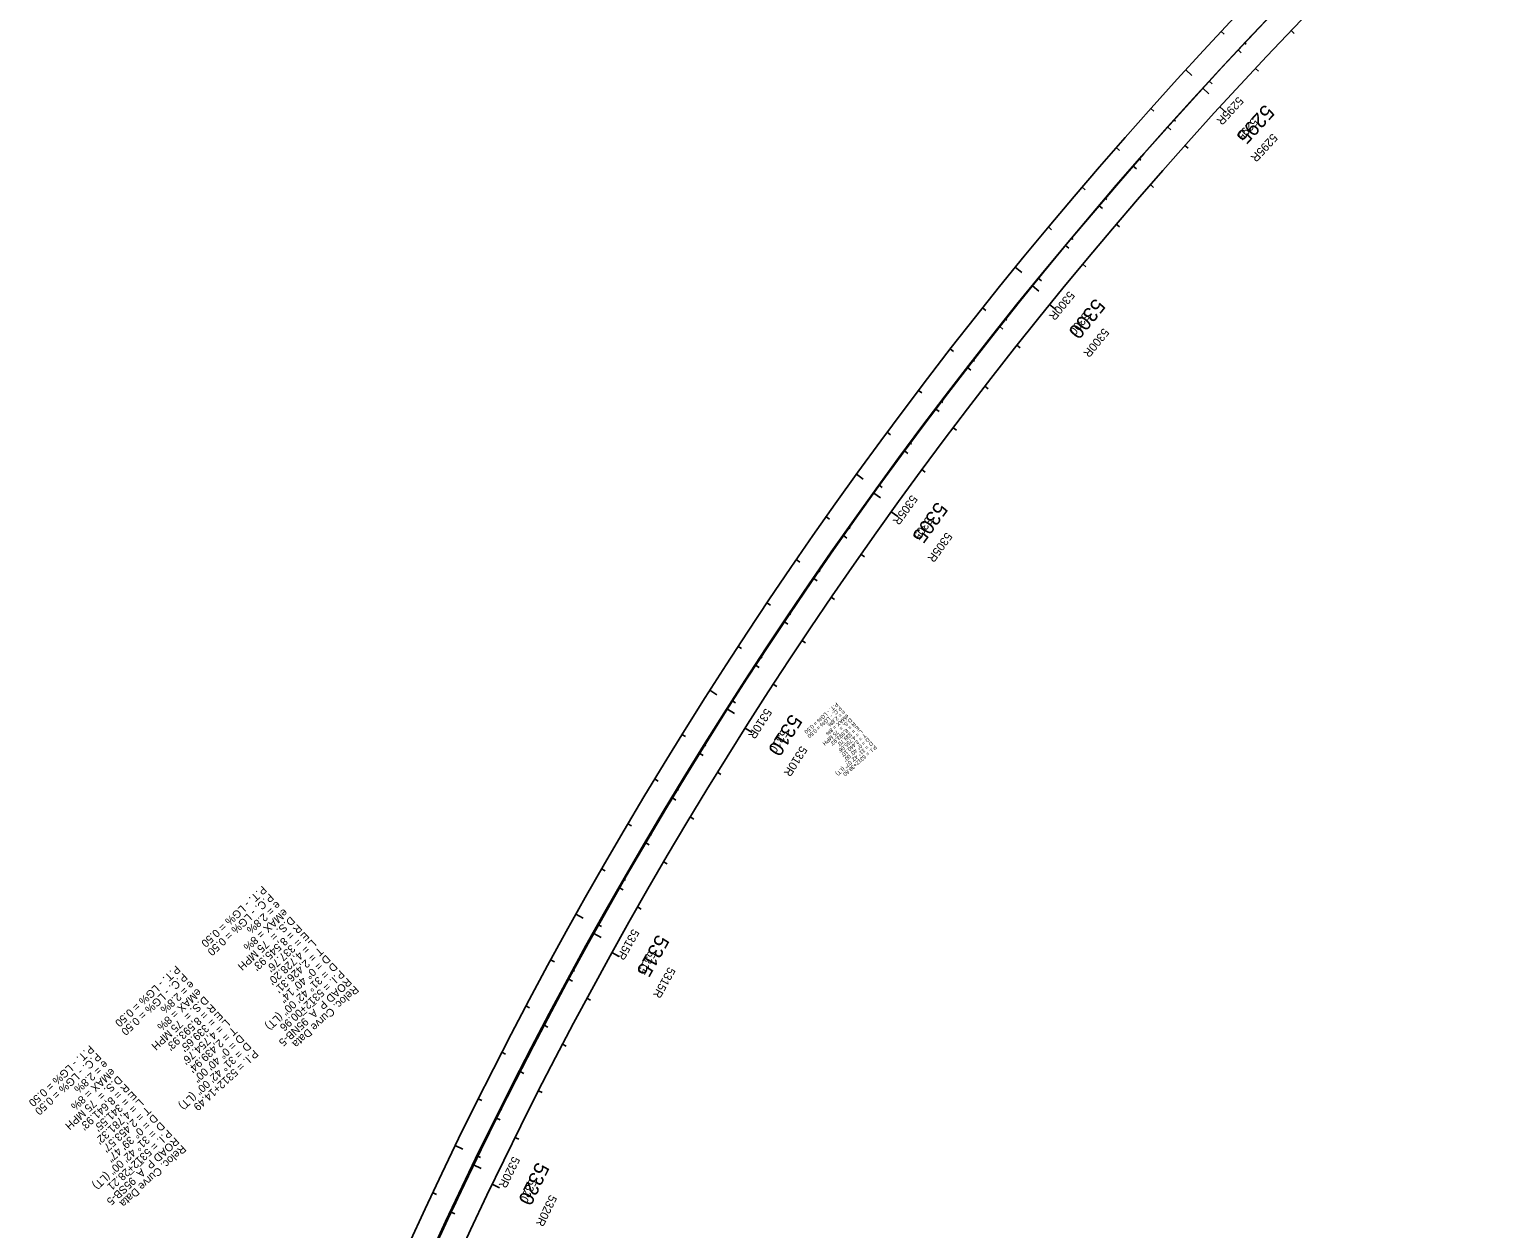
# Model space of a CAD drawing. Extents: x 2160876 to 2175990, y 601436 to 618246.
# Drawn here: x 2160945 to 2163737, y 603160 to 605458 of the extents above; entities that cross this region are included whole.
import ezdxf

# ---------------------------------------------------------------- set-up
doc = ezdxf.new("R2010")
doc.units = 0
for name, color, linetype in [('BNDY-ADJ', 7, 'Continuous'), ('BNDY-ADJ-TXT', 7, 'Continuous'), ('RD_DTM_Major2', 7, 'Continuous'), ('RD_EX_BldgApp_Steps', 7, 'Continuous'), ('RD_EX_DV_TX_Prop', 7, 'Continuous'), ('RD_EX_Parking_Conc', 7, 'Continuous'), ('RD_HC_Cl', 7, 'Continuous'), ('RD_HC_Data_Tic', 7, 'Continuous'), ('RD_HC_TX_Sta50', 7, 'Continuous')]:
    doc.layers.add(name, color=color, linetype=linetype)

msp = doc.modelspace()

# ---------------------------------------------------------------- linework, layer by layer
at = {"layer": 'BNDY-ADJ'}
msp.add_arc((2169535, 599544.7), 8593.9, 132.71947, 164.41949, dxfattribs=at)
at = {"layer": 'BNDY-ADJ-TXT'}
for radius in [8641.9, 8545.9]:
    msp.add_arc((2169535, 599544.7), radius, 132.71947, 164.41949, dxfattribs=at)
at = {"layer": 'RD_DTM_Major2'}
for p, q in [((2163261.1, 605417.9), (2163267, 605412.4)), ((2163193.2, 605344.5), (2163205, 605333.7)), ((2163126.2, 605270.3), (2163132.1, 605265)), ((2163060, 605195.4), (2163066, 605190.1)), ((2162994.7, 605119.6), (2163000.8, 605114.4)), ((2162930.2, 605043.2), (2162936.4, 605038)), ((2162866.7, 604965.9), (2162879.1, 604955.8)), ((2162804.1, 604888), (2162810.3, 604883)), ((2162742.4, 604809.3), (2162748.7, 604804.4)), ((2162681.6, 604729.9), (2162687.9, 604725.1)), ((2162621.7, 604649.8), (2162628.1, 604645)), ((2162562.8, 604569), (2162575.7, 604559.7)), ((2162504.8, 604487.5), (2162511.3, 604482.9)), ((2162447.7, 604405.4), (2162454.3, 604400.9)), ((2162391.7, 604322.6), (2162398.3, 604318.2)), ((2162336.5, 604239.2), (2162343.2, 604234.8)), ((2162282.4, 604155.1), (2162295.9, 604146.5)), ((2162229.3, 604070.4), (2162236.1, 604066.2)), ((2162177.1, 603985.1), (2162183.9, 603980.9)), ((2162125.9, 603899.2), (2162132.8, 603895.1)), ((2162075.8, 603812.7), (2162082.7, 603808.7)), ((2162026.6, 603725.6), (2162040.6, 603717.8)), ((2161978.5, 603637.9), (2161985.5, 603634.1)), ((2161931.3, 603549.7), (2161938.4, 603546)), ((2161885.3, 603461), (2161892.4, 603457.3)), ((2161840.2, 603371.7), (2161847.4, 603368.1)), ((2161796.2, 603281.9), (2161810.6, 603274.9)), ((2161753.2, 603191.6), (2161760.5, 603188.2))]:
    msp.add_line(p, q, dxfattribs=at)
at = {"layer": 'RD_EX_BldgApp_Steps'}
for p, q in [((2163273.3, 605431.5), (2163276.3, 605428.8)), ((2163205.2, 605358.3), (2163211.1, 605352.9)), ((2163138, 605284.3), (2163140.9, 605281.6)), ((2163071.6, 605209.5), (2163074.6, 605206.9)), ((2163006, 605134), (2163009.1, 605131.4)), ((2162941.4, 605057.7), (2162944.5, 605055.1)), ((2162877.7, 604980.6), (2162883.9, 604975.6)), ((2162814.8, 604902.8), (2162817.9, 604900.4)), ((2162752.9, 604824.3), (2162756, 604821.9)), ((2162691.9, 604745.1), (2162695, 604742.7)), ((2162631.8, 604665.2), (2162635, 604662.8)), ((2162572.6, 604584.6), (2162579.1, 604579.9)), ((2162514.4, 604503.3), (2162517.7, 604500.9)), ((2162457.1, 604421.3), (2162460.4, 604419)), ((2162400.8, 604338.6), (2162404.1, 604336.4)), ((2162345.5, 604255.4), (2162348.8, 604253.2)), ((2162291.1, 604171.4), (2162297.8, 604167.1)), ((2162237.7, 604086.9), (2162241.1, 604084.8)), ((2162185.3, 604001.7), (2162188.7, 603999.6)), ((2162133.9, 603915.9), (2162137.3, 603913.9)), ((2162083.5, 603829.6), (2162087, 603827.6)), ((2162034.1, 603742.6), (2162041.1, 603738.7)), ((2161985.7, 603655.1), (2161989.2, 603653.2)), ((2161938.3, 603567), (2161941.9, 603565.2)), ((2161892, 603478.4), (2161895.6, 603476.6)), ((2161846.7, 603389.3), (2161850.3, 603387.5)), ((2161802.5, 603299.6), (2161809.7, 603296.1)), ((2161759.2, 603209.4), (2161762.9, 603207.7))]:
    msp.add_line(p, q, dxfattribs=at)
msp.add_arc((2169530.8, 599540.9), 8593.9, 132.71947, 164.42145, dxfattribs=at)
at = {"layer": 'RD_HC_Cl'}
for p, q in [((2163228.5, 605453.3), (2163234.4, 605447.9)), ((2163362.6, 605455.2), (2163368.4, 605449.7)), ((2163160.6, 605380), (2163172.4, 605369.2)), ((2163293.9, 605382.6), (2163299.7, 605377.2)), ((2163093.5, 605305.8), (2163099.5, 605300.5)), ((2163226, 605309.2), (2163237.8, 605298.4)), ((2163027.3, 605230.9), (2163033.3, 605225.6)), ((2163159, 605235), (2163164.9, 605229.6)), ((2162961.9, 605155.2), (2162968, 605150)), ((2163092.8, 605160), (2163098.8, 605154.7)), ((2163027.5, 605084.2), (2163033.6, 605079)), ((2162897.4, 605078.8), (2162903.6, 605073.6)), ((2162833.8, 605001.6), (2162846.2, 604991.5)), ((2162963.2, 605007.7), (2162969.3, 605002.6)), ((2162771.1, 604923.7), (2162777.4, 604918.7)), ((2162899.7, 604930.4), (2162912.1, 604920.3)), ((2162709.4, 604845.1), (2162715.7, 604840.2)), ((2162837.1, 604852.4), (2162843.4, 604847.4)), ((2162775.5, 604773.7), (2162781.8, 604768.8)), ((2162648.5, 604765.7), (2162654.9, 604760.9)), ((2162714.8, 604694.2), (2162721.1, 604689.4)), ((2162588.5, 604685.7), (2162595, 604680.9)), ((2162655, 604614.1), (2162661.4, 604609.3)), ((2162529.5, 604605), (2162542.5, 604595.6)), ((2162471.4, 604523.6), (2162478, 604519)), ((2162596.1, 604533.2), (2162609.1, 604523.9)), ((2162414.3, 604441.5), (2162420.9, 604437)), ((2162538.2, 604451.7), (2162544.8, 604447.1)), ((2162358.1, 604358.8), (2162364.7, 604354.3)), ((2162481.3, 604369.5), (2162487.9, 604364.9)), ((2162302.9, 604275.4), (2162309.6, 604271)), ((2162425.3, 604286.6), (2162432, 604282.2)), ((2162248.6, 604191.4), (2162262.1, 604182.8)), ((2162370.3, 604203.1), (2162377, 604198.7)), ((2162195.3, 604106.8), (2162202.1, 604102.6)), ((2162316.3, 604118.9), (2162329.8, 604110.4)), ((2162143, 604021.5), (2162149.9, 604017.4)), ((2162263.3, 604034.1), (2162270.1, 604029.9)), ((2162091.7, 603935.7), (2162098.6, 603931.6)), ((2162211.2, 603948.7), (2162218.1, 603944.6)), ((2162160.2, 603862.8), (2162167.1, 603858.7)), ((2162041.4, 603849.3), (2162048.4, 603845.3)), ((2162110.2, 603776.2), (2162117.1, 603772.2)), ((2161992.1, 603762.3), (2162006.1, 603754.5)), ((2162061.2, 603689), (2162075.2, 603681.2)), ((2161943.8, 603674.7), (2161950.9, 603670.9)), ((2162013.2, 603601.3), (2162020.2, 603597.5)), ((2161896.5, 603586.6), (2161903.6, 603582.9)), ((2161850.3, 603498), (2161857.4, 603494.3)), ((2161966.3, 603513), (2161973.3, 603509.2)), ((2161805.1, 603408.8), (2161812.2, 603405.2)), ((2161920.3, 603424.1), (2161927.5, 603420.5)), ((2161875.5, 603334.8), (2161882.6, 603331.2)), ((2161760.9, 603319.1), (2161775.3, 603312.1)), ((2161831.6, 603244.9), (2161846.1, 603237.9)), ((2161717.7, 603228.9), (2161724.9, 603225.4))]:
    msp.add_line(p, q, dxfattribs=at)

# ---------------------------------------------------------------- texts
at = {"layer": 'RD_EX_BldgApp_Steps'}
for s, height, rotation, p in [('5295', 28, 227.3964, (2163312.3, 605315.2)), ('5300', 28, 230.7299, (2162987.1, 604943.9)), ('5305', 28, 234.0634, (2162684, 604554.2)), ('P.T. - LG% = 0.50', 7.5, 221.9367, (2162491, 604168.4)), ('P.C. - LG% = 0.50', 7.5, 221.9367, (2162497.7, 604160.9)), ('5310', 28, 237.3969, (2162404.1, 604147.6)), ('D.S. =  75 MPH ', 7.5, 221.9367, (2162517.7, 604138.6)), ('eMAX = 8%', 7.5, 221.9367, (2162511, 604146)), ('e = 2.8%', 7.5, 221.9367, (2162504.3, 604153.5)), ("R = 8,593.93'", 7.5, 221.9367, (2162524.4, 604131.2)), ("E = 339.70'", 7.5, 221.9367, (2162531.1, 604123.7)), ("L = 4,755.06'", 7.5, 221.9367, (2162537.8, 604116.3)), ("T = 2,440.10'", 7.5, 221.9367, (2162544.4, 604108.8)), ('    = 31° 42\' 07" (LT)', 7.5, 221.9367, (2162557.8, 604094)), ('P.I. = 5312+38.60', 7.5, 221.9367, (2162564.5, 604086.5)), ('D = 0° 40\' 00"', 7.5, 221.9367, (2162551.1, 604101.4)), ('D', 7.5, 221.9367, (2162557.8, 604094)), ('5315', 28, 240.7304, (2162148.2, 603725.3)), ('5320', 28, 244.0639, (2161917.4, 603289.1))]:
    msp.add_text(s, height=height, rotation=rotation, dxfattribs=at).set_placement(p)
at = {"layer": 'RD_EX_DV_TX_Prop'}
for s, rotation, p in [('5295', 227.556, (2163288.9, 605289.1)), ('5300', 230.8895, (2162965.7, 604916.6)), ('5305', 234.223, (2162664.2, 604525.1)), ('5310', 237.5565, (2162386.5, 604117.5)), ('5315', 240.8901, (2162132.5, 603693.7)), ('5320', 244.2236, (2161904, 603256.7))]:
    msp.add_text(s, height=16, rotation=rotation, dxfattribs=at).set_placement(p)
at = {"layer": 'RD_EX_Parking_Conc'}
for s, p in [('P.T. - LG% = 0.50', (2161226.2, 603665.1)), ('P.C. - LG% = 0.50', (2161239.7, 603650.4)), ('e = 2.8%', (2161253.3, 603635.7)), ('D.S. =  75 MPH', (2161280.4, 603606.3)), ('eMAX = 8%', (2161266.9, 603621)), ("R = 8,593.93'", (2161294, 603591.6)), ("E = 339.65'", (2161307.6, 603576.9)), ("L = 4,754.76'", (2161321.1, 603562.2)), ("T = 2,439.94'", (2161334.7, 603547.5)), ('D = 0° 40\' 00"', (2161348.3, 603532.8)), ('D', (2161361.8, 603518.2)), ('    = 31° 42\' 00" (LT)', (2161361.8, 603518.2)), ('P.I. = 5312+14.49', (2161375.4, 603503.5))]:
    msp.add_text(s, height=15, rotation=222.7195, dxfattribs=at).set_placement(p)
at = {"layer": 'RD_HC_Data_Tic'}
for s, rotation, p in [('5295R', 227.5286, (2163261, 605329.7)), ('5295R', 227.5826, (2163326.4, 605259)), ('5300R', 230.8435, (2162937, 604957.2)), ('5300R', 230.9348, (2163002.9, 604886.2)), ('5305R', 234.1585, (2162635.1, 604566.7)), ('5305R', 234.287, (2162701.8, 604495.1)), ('5310R', 237.4735, (2162355.4, 604158)), ('5310R', 237.6393, (2162423.2, 604085.9)), ('5315R', 240.7885, (2162100.7, 603735.2)), ('5315R', 240.9915, (2162169.9, 603662.3)), ('5320R', 244.1035, (2161871.4, 603299.5)), ('5320R', 244.3437, (2161942.3, 603225.8))]:
    msp.add_text(s, height=16, rotation=rotation, dxfattribs=at).set_placement(p)
at = {"layer": 'RD_HC_TX_Sta50'}
for s, p in [('P.T. - LG% = 0.50', (2161391.5, 603817.7)), ('P.C. - LG% = 0.50', (2161405, 603803)), ('eMAX = 8%', (2161432.2, 603773.7)), ('e = 2.8%', (2161418.6, 603788.3)), ('D.S. =  75 MPH', (2161445.7, 603759)), ("R = 8,545.93'", (2161459.3, 603744.3)), ("E = 337.76'", (2161472.9, 603729.6)), ("L = 4,728.20'", (2161486.4, 603714.9)), ("T = 2,426.31'", (2161500, 603700.2)), ('D = 0° 40\' 14"', (2161513.6, 603685.5)), ('D', (2161527.2, 603670.8)), ('    = 31° 42\' 00" (LT)', (2161527.2, 603670.8)), ('ROAD P_A_95NB-5', (2161554.3, 603641.4)), ('P.I. = 5312+00.96', (2161540.7, 603656.1)), ('Reloc. Curve Data', (2161567.9, 603626.7)), ('P.T. - LG% = 0.50', (2161060.9, 603512.4)), ('P.C. - LG% = 0.50', (2161074.4, 603497.8)), ('eMAX = 8%', (2161101.6, 603468.4)), ('e = 2.8%', (2161088, 603483.1)), ('D.S. =  75 MPH', (2161115.1, 603453.7)), ("R = 8,641.93'", (2161128.7, 603439)), ("E = 341.55'", (2161142.3, 603424.3)), ("L = 4,781.32'", (2161155.8, 603409.6)), ("T = 2,453.57'", (2161169.4, 603394.9)), ('D = 0° 39\' 47"', (2161183, 603380.2)), ('P.I. = 5312+28.21', (2161210.1, 603350.8)), ('D', (2161196.5, 603365.5)), ('    = 31° 42\' 00" (LT)', (2161196.5, 603365.5)), ('ROAD P_A_95SB-5', (2161223.7, 603336.1)), ('Reloc. Curve Data', (2161237.2, 603321.4))]:
    msp.add_text(s, height=15, rotation=222.7195, dxfattribs=at).set_placement(p)

doc.saveas('drawing.dxf')
